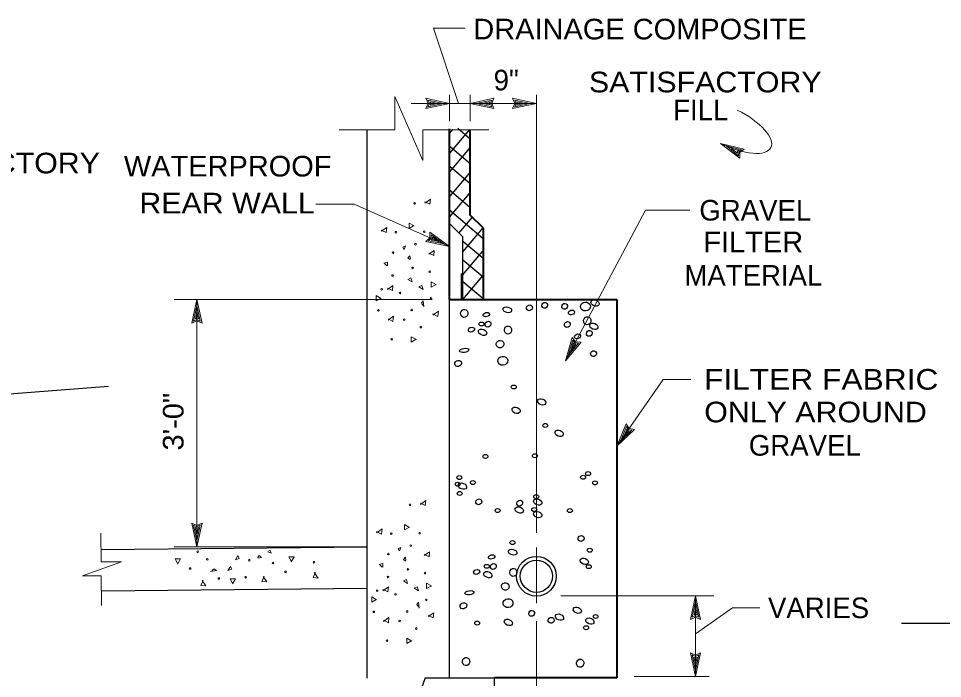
# Model space of a CAD drawing. Extents: x -22.3 to 19.7, y -11.8 to 18.2.
# Drawn here: x -0.15 to 5.45, y -8.88 to -4.88 of the extents above; entities that cross this region are included whole.
import ezdxf
from ezdxf.enums import TextEntityAlignment as Align

# ---------------------------------------------------------------- set-up
doc = ezdxf.new("R2010")
doc.units = 0
doc.header["$LTSCALE"] = 0.05
doc.layers.add('1', color=7, linetype='Continuous', lineweight=13)
doc.layers.add('2', color=7, linetype='Continuous', lineweight=13)

msp = doc.modelspace()

# ---------------------------------------------------------------- linework, layer by layer
at = {"layer": '1'}
for p, q in [((2.13258, -5.55069), (2.13258, -5.34869)), ((2.30158, -5.73669), (2.13258, -5.34869)), ((2.46458, -5.39069), (2.32058, -5.35969)), ((2.42758, -5.39069), (2.33358, -5.37069)), ((2.34258, -5.39069), (2.33358, -5.37069)), ((2.46458, -5.33769), (2.46458, -5.49769)), ((2.58958, -5.33769), (2.58958, -5.49769)), ((2.58958, -5.39069), (2.73358, -5.35969)), ((2.62658, -5.39069), (2.72058, -5.37069)), ((2.72058, -5.37069), (2.71158, -5.39069)), ((2.99058, -5.39069), (2.84658, -5.35969)), ((2.95358, -5.39069), (2.85958, -5.37069)), ((2.86858, -5.39069), (2.85958, -5.37069)), ((2.99058, -5.33769), (2.99058, -7.99269)), ((2.46458, -5.39069), (2.32058, -5.42169)), ((2.42758, -5.39069), (2.33358, -5.41069)), ((2.33358, -5.41069), (2.34258, -5.39069)), ((2.39158, -5.39069), (2.34658, -5.38169)), ((2.35058, -5.39069), (2.34658, -5.38169)), ((2.39158, -5.39069), (2.34658, -5.40069)), ((2.34658, -5.40069), (2.35058, -5.39069)), ((2.58958, -5.39069), (2.99058, -5.39069)), ((2.58958, -5.39069), (2.73358, -5.42169)), ((2.62658, -5.39069), (2.72058, -5.41069)), ((2.66258, -5.39069), (2.70758, -5.38069)), ((2.66258, -5.39069), (2.70758, -5.39969)), ((2.70758, -5.38069), (2.70358, -5.39069)), ((2.70358, -5.39069), (2.70758, -5.39969)), ((2.71158, -5.39069), (2.72058, -5.41069)), ((2.99058, -5.39069), (2.84658, -5.42169)), ((2.95358, -5.39069), (2.85958, -5.41069)), ((2.85958, -5.41069), (2.86858, -5.39069)), ((2.91758, -5.39069), (2.87258, -5.38169)), ((2.87658, -5.39069), (2.87258, -5.38169)), ((2.91758, -5.39069), (2.87258, -5.40069)), ((2.87258, -5.40069), (2.87658, -5.39069)), ((1.79458, -5.55069), (2.13258, -5.55069)), ((2.30158, -5.73669), (2.30158, -5.55069)), ((2.30158, -5.55069), (2.70158, -5.55069)), ((4.10658, -5.63269), (4.24958, -5.66769)), ((4.10658, -5.63269), (4.22258, -5.72269)), ((4.13958, -5.64869), (4.23358, -5.67169)), ((4.13958, -5.64869), (4.21558, -5.70769)), ((4.17258, -5.66469), (4.20858, -5.69169)), ((4.17258, -5.66469), (4.21758, -5.67469)), ((4.20958, -5.68169), (4.20858, -5.69169)), ((4.21758, -5.67469), (4.20958, -5.68169)), ((4.21658, -5.68569), (4.21558, -5.70769)), ((4.23358, -5.67169), (4.21658, -5.68569)), ((2.33658, -6.22269), (2.35258, -6.20769)), ((2.46458, -6.25769), (2.34558, -6.17069)), ((2.43058, -6.24269), (2.35258, -6.18669)), ((2.35258, -6.20769), (2.35258, -6.18669)), ((2.35258, -6.21869), (2.36058, -6.21169)), ((2.39758, -6.22769), (2.36058, -6.20169)), ((2.36058, -6.21169), (2.36058, -6.20169)), ((2.46458, -6.25769), (2.32058, -6.22769)), ((2.43058, -6.24269), (2.33658, -6.22269)), ((2.39758, -6.22769), (2.35258, -6.21869)), ((2.35958, -6.57869), (0.79658, -6.57869)), ((0.93358, -6.57869), (0.90258, -6.72269)), ((0.93358, -6.61569), (0.91358, -6.70969)), ((0.93358, -6.65169), (0.92458, -6.69669)), ((0.93358, -6.61569), (0.95358, -6.70969)), ((0.93358, -6.65169), (0.94358, -6.69669)), ((0.93358, -6.70069), (0.91358, -6.70969)), ((0.93358, -6.69269), (0.92458, -6.69669)), ((0.94358, -6.69669), (0.93358, -6.69269)), ((0.95358, -6.70969), (0.93358, -6.70069)), ((3.16658, -6.95069), (3.20658, -6.80869)), ((3.18358, -6.91769), (3.21058, -6.82569)), ((3.21058, -6.82569), (3.22358, -6.84269)), ((3.16658, -6.95069), (3.26158, -6.83769)), ((3.18358, -6.91769), (3.24558, -6.84469)), ((3.20058, -6.88669), (3.21258, -6.84169)), ((3.20058, -6.88669), (3.22958, -6.85069)), ((3.21258, -6.84169), (3.21958, -6.84969)), ((3.21958, -6.84969), (3.22958, -6.85069)), ((3.22358, -6.84269), (3.24558, -6.84469)), ((3.47858, -7.46869), (3.53458, -7.33269)), ((3.47858, -7.46869), (3.58558, -7.36769)), ((3.49958, -7.43869), (3.53658, -7.34969)), ((3.49958, -7.43869), (3.56958, -7.37169)), ((3.51958, -7.40869), (3.53758, -7.36569)), ((3.51958, -7.40869), (3.55258, -7.37669)), ((3.53658, -7.34969), (3.54758, -7.36869)), ((3.53758, -7.36569), (3.54358, -7.37469)), ((3.54358, -7.37469), (3.55258, -7.37669)), ((3.54758, -7.36869), (3.56958, -7.37169)), ((0.93358, -8.07869), (0.90258, -7.93469)), ((0.93358, -8.04169), (0.91358, -7.94769)), ((0.91358, -7.94769), (0.93358, -7.95669)), ((0.93358, -8.07869), (0.96458, -7.93469)), ((0.93358, -8.04169), (0.95358, -7.94769)), ((0.93358, -7.95669), (0.95358, -7.94769)), ((0.35458, -8.16969), (0.35258, -7.99469)), ((0.93358, -8.00569), (0.92358, -7.96069)), ((0.92358, -7.96069), (0.93358, -7.96469)), ((0.93358, -8.00569), (0.94258, -7.96069)), ((0.93358, -7.96469), (0.94258, -7.96069)), ((1.96458, -8.07869), (0.79658, -8.07869)), ((2.99058, -8.08269), (2.99058, -8.42069)), ((0.24058, -8.25369), (0.47758, -8.16969)), ((0.35458, -8.16969), (0.47758, -8.16969)), ((0.24058, -8.25369), (0.35458, -8.25369)), ((0.35658, -8.43369), (0.35458, -8.25369)), ((3.13858, -8.37469), (4.06458, -8.37469)), ((3.95458, -8.37469), (3.92358, -8.51869)), ((3.95458, -8.86469), (3.95458, -8.37469)), ((3.95458, -8.37469), (3.98558, -8.51869)), ((3.95458, -8.41169), (3.93458, -8.50569)), ((3.95458, -8.44769), (3.94558, -8.49269)), ((3.95458, -8.41169), (3.97458, -8.50569)), ((3.95458, -8.44769), (3.96458, -8.49269)), ((3.95458, -8.49669), (3.93458, -8.50569)), ((3.95458, -8.48869), (3.94558, -8.49269)), ((3.96458, -8.49269), (3.95458, -8.48869)), ((3.97458, -8.50569), (3.95458, -8.49669)), ((2.99058, -8.52869), (2.99058, -9.64669)), ((3.95458, -8.86469), (3.92358, -8.72069)), ((3.95458, -8.86469), (3.98558, -8.72069)), ((3.95458, -8.82769), (3.93458, -8.73369)), ((3.93458, -8.73369), (3.95458, -8.74269)), ((3.95458, -8.79169), (3.94458, -8.74669)), ((3.94458, -8.74669), (3.95458, -8.75069)), ((3.95458, -8.82769), (3.97458, -8.73369)), ((3.95458, -8.74269), (3.97458, -8.73369)), ((3.95458, -8.79169), (3.96358, -8.74669)), ((3.95458, -8.75069), (3.96358, -8.74669)), ((3.58258, -8.86469), (4.03758, -8.86469))]:
    msp.add_line(p, q, dxfattribs=at)
at = {"layer": '1', "lineweight": 25}
for p, q in [((1.96458, -8.87469), (1.96458, -5.55069)), ((2.46358, -5.57369), (2.48658, -5.54669)), ((2.46458, -8.87469), (2.46458, -5.55069)), ((2.46658, -5.69269), (2.58758, -5.54969)), ((2.58958, -5.60769), (2.51358, -5.54269)), ((2.58958, -5.75669), (2.46758, -5.65369)), ((2.46658, -5.80469), (2.58758, -5.66169)), ((2.58958, -5.87869), (2.46758, -5.77569)), ((2.46758, -5.95269), (2.58858, -5.80969)), ((2.58558, -6.01869), (2.46358, -5.91569)), ((2.46358, -6.07969), (2.58458, -5.93669)), ((2.66858, -6.21069), (2.46358, -6.03869)), ((2.52058, -6.17669), (2.60258, -6.08069)), ((2.54458, -6.19869), (2.46858, -6.12269)), ((2.54658, -6.28769), (2.66758, -6.14469)), ((2.54458, -6.57869), (2.54458, -6.19869)), ((2.66558, -6.32869), (2.54458, -6.22669)), ((2.54358, -6.43169), (2.66458, -6.28869)), ((2.66558, -6.44269), (2.54458, -6.34069)), ((2.54458, -6.57869), (2.66558, -6.43569)), ((2.66558, -6.57369), (2.54458, -6.47169)), ((0.35358, -8.09469), (1.96458, -8.07869)), ((0.35558, -8.34469), (1.96458, -8.32869)), ((5.20158, -8.54069), (8.04558, -8.54069)), ((2.31658, -8.87269), (2.29458, -8.93469)), ((2.31658, -8.87269), (2.73658, -8.87269)), ((2.73658, -9.38269), (2.73658, -8.87269))]:
    msp.add_line(p, q, dxfattribs=at)
at = {"layer": '1', "lineweight": 40}
for p, q in [((2.46458, -6.57869), (2.46458, -5.54469)), ((2.66958, -6.57869), (2.66958, -6.14769)), ((2.53958, -6.57869), (2.53958, -6.42169)), ((2.46458, -6.57869), (3.47858, -6.57869)), ((3.47858, -6.57869), (3.47858, -8.87269)), ((3.47858, -8.87269), (2.73658, -8.87269))]:
    msp.add_line(p, q, dxfattribs=at)
at = {"layer": '1'}
for points in [[(2.51858, -5.39069), (2.36658, -4.93469), (2.55858, -4.93469)], [(2.32058, -5.42169), (2.33458, -5.39069), (2.32058, -5.35969)], [(2.73358, -5.35969), (2.71958, -5.39069), (2.73358, -5.42169)], [(2.84658, -5.42169), (2.86058, -5.39069), (2.84658, -5.35969)], [(2.58958, -5.39069), (2.46458, -5.39069), (2.23158, -5.39069)], [(4.24958, -5.66769), (4.22358, -5.68869), (4.22258, -5.72269)], [(2.46458, -6.25769), (1.88558, -6.00069), (1.65358, -6.00069)], [(3.16658, -6.95069), (3.65058, -6.03869), (3.92058, -6.03869)], [(2.32058, -6.22769), (2.34558, -6.20469), (2.34558, -6.17069)], [(0.93358, -8.07869), (0.93358, -6.57869), (0.96458, -6.72269)], [(0.96458, -6.72269), (0.93358, -6.70869), (0.90258, -6.72269)], [(3.20658, -6.80869), (3.22758, -6.83569), (3.26158, -6.83769)], [(3.47858, -7.46869), (3.75758, -7.06369), (3.92658, -7.06369)], [(3.53458, -7.33269), (3.55258, -7.36169), (3.58558, -7.36769)], [(0.90258, -7.93469), (0.93358, -7.94869), (0.96458, -7.93469)], [(3.95458, -8.60569), (4.17958, -8.44869), (4.34358, -8.44869)], [(3.98558, -8.51869), (3.95458, -8.50469), (3.92358, -8.51869)], [(3.92358, -8.72069), (3.95458, -8.73469), (3.98558, -8.72069)]]:
    msp.add_lwpolyline(points, dxfattribs=at)
at = {"layer": '1', "lineweight": 40}
msp.add_lwpolyline([(2.66958, -6.14769), (2.58958, -6.06769), (2.58958, -5.55069)], dxfattribs=at)
at = {"layer": '1', "lineweight": 25}
msp.add_lwpolyline([(0.39758, -7.10569), (-2.91642, -7.36269), (-2.63442, -7.27869)], dxfattribs=at)
for radius in [0.12021, 0.09759]:
    msp.add_circle((2.99058, -8.25669), radius, dxfattribs=at)
at = {"layer": '1'}
msp.add_ellipse((4.15708, -5.53169), major_axis=(0.25396, -0.12698), ratio=0.397704, start_param=4.712389, end_param=7.8539816, dxfattribs=at)
at = {"layer": '1', "lineweight": 25}
for centre, major_axis, ratio in [((3.04058, -6.61469), (0.01404, 0.01188), 0.925744), ((3.16158, -6.62069), (0.01404, 0.01188), 0.925744), ((3.28758, -6.62169), (0.03, 0.003), 0.895325), ((3.34558, -6.60069), (0.024, -0.01), 0.691328), ((2.55358, -6.66369), (0.0033, 0.02423), 0.908016), ((2.68758, -6.67069), (0.019, 0.005), 0.642337), ((2.81458, -6.64169), (0.026, -0.006), 0.637098), ((2.94858, -6.62969), (0.01404, 0.01188), 0.925744), ((3.20358, -6.65769), (0.018, 0.006), 0.73994), ((2.65758, -6.72769), (0.015, 0), 0.801784), ((2.69758, -6.72869), (0.01404, 0.01188), 0.925744), ((3.17758, -6.73069), (0.01404, 0.01188), 0.925744), ((3.29858, -6.70769), (0.0033, 0.02423), 0.908016), ((2.59658, -6.76169), (0.018, 0.006), 0.73994), ((2.66458, -6.77769), (0.024, -0.01), 0.691328), ((2.81858, -6.76469), (0.0033, 0.02423), 0.908016), ((3.31158, -6.78469), (0.01404, 0.01188), 0.925744), ((3.33858, -6.74169), (0.024, -0.01), 0.691328), ((2.76958, -6.84969), (0.023, -0.004), 0.985988), ((3.23958, -6.80269), (0.018, 0.006), 0.73994), ((2.55258, -6.88769), (0.028, 0.004), 0.441415), ((2.78658, -6.95069), (0.03, 0.003), 0.895325), ((3.33658, -6.90769), (0.01404, 0.01188), 0.925744), ((2.51658, -6.96669), (0.018, 0.011), 0.849447), ((2.85358, -7.10969), (0.015, 0), 0.801784), ((3.02258, -7.19969), (0.024, -0.01), 0.691328), ((2.86758, -7.25069), (0.024, -0.01), 0.691328), ((3.04458, -7.34269), (0.015, 0), 0.801784), ((3.12858, -7.39069), (0.024, -0.01), 0.691328), ((2.68158, -7.53069), (0.015, 0), 0.801784), ((2.98158, -7.52669), (0.015, 0), 0.801784), ((2.52358, -7.65869), (0.015, 0), 0.801784), ((3.27358, -7.65669), (0.015, 0), 0.801784), ((3.30358, -7.63469), (0.015, 0), 0.801784), ((2.51358, -7.69869), (0.015, 0), 0.801784), ((2.54258, -7.71069), (0.024, -0.01), 0.691328), ((2.60558, -7.68869), (0.015, 0), 0.801784), ((3.34558, -7.69069), (0.015, 0), 0.801784), ((2.52558, -7.75469), (0.015, 0), 0.801784), ((2.98958, -7.77469), (0.015, 0), 0.801784), ((2.64158, -7.80569), (0.01404, 0.01188), 0.925744), ((2.88658, -7.85469), (0.024, -0.01), 0.691328), ((2.88958, -7.81369), (0.01404, 0.01188), 0.925744), ((2.99858, -7.80669), (0.024, -0.01), 0.691328), ((2.75558, -7.85869), (0.015, 0), 0.801784), ((2.97758, -7.85269), (0.015, 0), 0.801784), ((2.99858, -7.88269), (0.024, -0.01), 0.691328), ((3.19358, -7.85869), (0.015, 0), 0.801784), ((2.84558, -8.05269), (0.015, 0), 0.801784), ((3.26158, -8.02769), (0.01404, 0.01188), 0.925744), ((2.84658, -8.11069), (0.026, -0.006), 0.637098), ((3.31358, -8.09869), (0.015, 0), 0.801784), ((2.71958, -8.13969), (0.019, 0.005), 0.642337), ((3.28058, -8.16669), (0.024, -0.01), 0.691328), ((2.62858, -8.23069), (0.018, 0.006), 0.73994), ((2.69658, -8.24669), (0.024, -0.01), 0.691328), ((2.68958, -8.19669), (0.015, 0), 0.801784), ((2.72958, -8.19769), (0.01404, 0.01188), 0.925744), ((2.85058, -8.23369), (0.0033, 0.02423), 0.908016), ((3.30758, -8.19869), (0.015, 0), 0.801784), ((2.80158, -8.31869), (0.023, -0.004), 0.985988), ((2.58458, -8.35669), (0.028, 0.004), 0.441415), ((2.81858, -8.41969), (0.03, 0.003), 0.895325), ((2.54858, -8.43569), (0.018, 0.011), 0.849447), ((3.23858, -8.46269), (0.024, -0.01), 0.691328), ((2.96158, -8.48169), (0.01404, 0.01188), 0.925744), ((3.07958, -8.52369), (0.01404, 0.01188), 0.925744), ((3.13058, -8.50469), (0.024, -0.01), 0.691328), ((3.31458, -8.52869), (0.024, -0.01), 0.691328), ((3.34958, -8.50069), (0.015, 0), 0.801784), ((2.63158, -8.54069), (0.015, 0), 0.801784), ((2.82058, -8.53669), (0.024, -0.01), 0.691328), ((3.29158, -8.56869), (0.015, 0), 0.801784), ((2.56458, -8.77369), (0.0033, 0.02423), 0.908016), ((3.25558, -8.78369), (0.0033, 0.02423), 0.908016)]:
    msp.add_ellipse(centre, major_axis=major_axis, ratio=ratio, dxfattribs=at)
at = {"layer": '2'}
for p, q in [((2.08358, -6.37569), (2.06858, -6.35869)), ((2.05558, -8.20269), (2.04058, -8.18569))]:
    msp.add_line(p, q, dxfattribs=at)
for points in [[(2.31558, -5.98669), (2.34558, -6.00169), (2.34858, -5.97069), (2.31558, -5.99469)], [(2.05058, -6.15869), (2.08058, -6.17369), (2.08358, -6.14269), (2.05058, -6.16569)], [(2.24558, -6.13369), (2.21958, -6.14869), (2.21958, -6.11569), (2.25058, -6.13369)], [(2.18658, -6.27669), (2.18158, -6.26169), (2.19758, -6.25469), (2.18958, -6.27669)], [(2.22458, -6.33769), (2.21258, -6.32769), (2.22458, -6.31469), (2.22758, -6.33469)], [(2.33858, -6.29769), (2.36858, -6.31269), (2.37158, -6.28169), (2.33858, -6.30469)], [(2.06558, -6.35869), (2.08858, -6.35269), (2.08858, -6.37569)], [(2.08858, -6.50969), (2.11858, -6.52469), (2.12158, -6.49369), (2.08858, -6.51769)], [(2.37858, -6.48969), (2.35358, -6.50469), (2.35358, -6.47169), (2.38458, -6.48969)], [(2.04558, -6.57269), (2.02058, -6.58769), (2.02058, -6.55469), (2.05058, -6.57269)], [(2.30358, -6.61569), (2.29358, -6.60069), (2.30358, -6.58769), (2.30858, -6.62269)], [(2.36358, -6.66669), (2.39358, -6.68169), (2.39658, -6.65069), (2.36358, -6.67369)], [(2.09158, -6.69669), (2.12158, -6.71169), (2.12458, -6.68069), (2.09158, -6.70369)], [(2.25858, -6.82269), (2.23258, -6.83769), (2.23258, -6.80469), (2.26358, -6.82269)], [(2.28758, -7.81369), (2.31758, -7.82869), (2.32058, -7.79769), (2.28758, -7.82169)], [(2.21758, -7.96069), (2.19158, -7.97569), (2.19158, -7.94269), (2.22258, -7.96069)], [(2.02258, -7.98569), (2.05258, -8.00069), (2.05558, -7.96969), (2.02258, -7.99269)], [(1.36258, -8.10569), (1.37758, -8.10069), (1.38458, -8.11669), (1.36258, -8.10869)], [(2.15858, -8.10369), (2.15358, -8.08869), (2.16958, -8.08169), (2.16158, -8.10369)], [(2.31058, -8.12469), (2.34058, -8.13969), (2.34358, -8.10869), (2.31058, -8.13169)], [(0.81658, -8.17769), (0.80158, -8.15169), (0.83458, -8.15169), (0.81658, -8.18269)], [(1.30158, -8.14369), (1.31158, -8.13169), (1.32458, -8.14369), (1.30458, -8.14669)], [(1.50558, -8.16469), (1.49058, -8.13869), (1.52358, -8.13869), (1.50558, -8.16969)], [(2.19658, -8.16469), (2.18458, -8.15469), (2.19658, -8.14169), (2.19958, -8.16169)], [(1.02358, -8.22269), (1.03858, -8.21269), (1.05158, -8.22269), (1.01658, -8.22769)], [(2.03758, -8.18569), (2.06058, -8.17969), (2.06058, -8.20269)], [(0.97258, -8.28269), (0.95758, -8.31269), (0.98858, -8.31569), (0.96558, -8.28269)], [(1.14958, -8.29769), (1.13458, -8.27269), (1.16758, -8.27269), (1.14958, -8.30369)], [(1.34158, -8.25769), (1.32658, -8.28769), (1.35758, -8.29069), (1.33458, -8.25769)], [(1.65258, -8.23469), (1.63758, -8.26469), (1.66858, -8.26769), (1.64458, -8.23469)], [(2.06058, -8.33669), (2.09058, -8.35169), (2.09358, -8.32069), (2.06058, -8.34469)], [(2.35058, -8.31669), (2.32558, -8.33169), (2.32558, -8.29869), (2.35658, -8.31669)], [(2.01758, -8.39969), (1.99258, -8.41469), (1.99258, -8.38169), (2.02258, -8.39969)], [(2.27558, -8.44269), (2.26558, -8.42769), (2.27558, -8.41469), (2.28058, -8.44969)], [(2.06358, -8.52369), (2.09358, -8.53869), (2.09658, -8.50769), (2.06358, -8.53069)], [(2.33558, -8.49369), (2.36558, -8.50869), (2.36858, -8.47769), (2.33558, -8.50069)], [(2.23058, -8.64969), (2.20458, -8.66469), (2.20458, -8.63169), (2.23558, -8.64969)]]:
    msp.add_lwpolyline(points, dxfattribs=at)
for points in [[(2.23858, -6.47269), (2.21258, -6.45769), (2.23058, -6.44869)], [(2.30358, -6.51769), (2.27758, -6.50269), (2.29558, -6.49369)], [(1.16658, -8.15769), (1.18158, -8.13169), (1.19058, -8.14969)], [(1.12158, -8.22269), (1.13658, -8.19669), (1.14558, -8.21469)], [(2.21058, -8.29969), (2.18458, -8.28469), (2.20258, -8.27569)], [(2.27558, -8.34469), (2.24958, -8.32969), (2.26758, -8.32069)]]:
    msp.add_lwpolyline(points, close=True, dxfattribs=at)
for centre in [(2.25246, -5.99669), (2.13921, -6.17144), (2.31096, -6.16844), (2.25771, -6.24419), (2.12196, -6.29519), (2.11896, -6.43394), (2.24046, -6.38819), (2.34396, -6.41069), (2.05371, -6.51719), (2.16471, -6.53969), (2.35146, -6.57269), (2.03346, -6.64544), (2.23521, -6.64319), (2.18946, -6.70094), (2.29071, -6.74669), (2.11371, -6.82019), (2.22446, -7.82369), (2.11121, -7.99844), (2.28296, -7.99544), (0.93833, -8.10856), (2.09396, -8.12219), (2.22971, -8.07119), (0.99608, -8.15431), (1.25108, -8.15956), (1.39508, -8.17681), (1.64258, -8.17156), (0.89258, -8.20981), (1.47083, -8.23006), (2.21246, -8.21519), (1.06658, -8.27056), (1.22858, -8.26306), (2.09096, -8.26094), (2.31596, -8.23769), (2.02571, -8.34419), (2.13671, -8.36669), (2.32346, -8.39969), (2.00546, -8.47244), (2.20721, -8.47019), (2.16146, -8.52794), (2.26271, -8.57369), (2.08571, -8.64719)]:
    msp.add_circle(centre, 0.00487, dxfattribs=at)

# ---------------------------------------------------------------- texts
at = {"layer": '1'}
for s, width, p in [('DRAINAGE COMPOSITE', 1.05, (2.60858, -5.00269)), ('FILTER FABRIC', 1.15, (4.00558, -7.12569))]:
    msp.add_text(s, height=0.125, dxfattribs=dict(at, width=width)).set_placement(p)
for s, p in [('9"', (2.80758, -5.31169)), ('MATERIAL', (4.30508, -6.49569)), ('GRAVEL', (4.61658, -7.52569))]:
    msp.add_text(s, height=0.125, dxfattribs=at).set_placement(p, align=Align.CENTER)
for s, width, p in [('SATISFACTORY', 1.1, (4.01358, -5.32369)), ('SATISFACTORY', 1.1, (-0.35842, -5.81469)), ('WATERPROOF', 1.05, (1.12008, -5.83369)), ('FILTER', 1.05, (4.30408, -6.29269)), ('ONLY AROUND', 1.1, (4.68158, -7.32369))]:
    msp.add_text(s, height=0.125, dxfattribs=dict(at, width=width)).set_placement(p, align=Align.CENTER)
msp.add_text('FILL', height=0.125, dxfattribs=at).set_placement((4.15358, -5.49269), align=Align.RIGHT)
at = {"layer": '1', "width": 1.1}
msp.add_text('REAR WALL', height=0.125, dxfattribs=at).set_placement((1.64758, -6.05769), align=Align.RIGHT)
at = {"layer": '1'}
for s, p in [('GRAVEL', (3.97758, -6.10069)), ('VARIES', (4.39358, -8.51069))]:
    msp.add_text(s, height=0.125, dxfattribs=at).set_placement(p)
at = {"layer": '1', "width": 1.05}
msp.add_text('3\'-0"', height=0.125, rotation=90, dxfattribs=at).set_placement((0.85258, -7.31969), align=Align.CENTER)

doc.saveas('drawing.dxf')
